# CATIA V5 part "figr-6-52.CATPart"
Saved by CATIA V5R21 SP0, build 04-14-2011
Part number: Part1
Bounding box of the stored display mesh (mm): x -46.66 to 43.071, y -43.071 to 47.059, z 0 to 20
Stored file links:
  D:\CATIA V5R21 E-RESOURCES\CATIA-V5R21\catia-v5r21-prt\c06-catia-v5r21-prt\c06-catia-v5r21-figr-6-52.CATPart
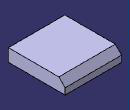
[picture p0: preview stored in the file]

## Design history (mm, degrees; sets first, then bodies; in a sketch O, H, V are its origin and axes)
Body1 (main body)
  Sketch1 on xy-plane, origin (0, 0, 0), H (1, 0, 0), V (0, 1, 0)
    line L1 (-46.6598, 47.0586) -> (43.0706, 47.0586)
    line L2 (43.0706, 47.0586) -> (43.0706, -43.0706)
    line L3 (43.0706, -43.0706) -> (-46.6598, -43.0706)
    line L4 (-46.6598, -43.0706) -> (-46.6598, 47.0586)
    horizontal: L1 H, L3 H
    vertical: L2 V, L4 V
  Pad1: profile Sketch1, direction (0, 0, 1), length 20
  Chamfer1: length 10, angle 45, on edge [face of Pad1 | face of Pad1]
